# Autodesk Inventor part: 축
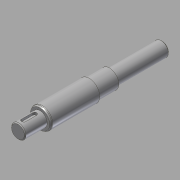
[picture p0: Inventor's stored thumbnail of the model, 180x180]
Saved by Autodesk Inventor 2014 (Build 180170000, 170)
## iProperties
Created: 2019-01
Part Number: 축
Material: 강철, 탄소
Document SubType Name: Modeling
Designer: mduedu
Density: 7.87 g/cm^3
Mass: 452.778 g
Surface Area: 120.904 cm^2
Volume: 57.5322 cm^3
Appearance: 강철
Author: mduedu
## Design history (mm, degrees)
sketch "스케치1"
  geometry: L1 (0, 0)-(26, 0); L2 (26, 0)-(26, 8.5); L3 (26, 8.5)-(0, 8.5); L4 (0, 8.5)-(0, 0); L5 (26, 0)-(84, 0); L6 (84, 0)-(84, 12.5); L7 (84, 12.5)-(26, 12.5); L8 (26, 12.5)-(26, 0); L9 (84, 0)-(108, 0); L10 (108, 0)-(108, 11); L11 (108, 11)-(84, 11); L12 (84, 11)-(84, 0); L13 (108, 0)-(170, 0); L14 (170, 0)-(170, 8.5); L15 (170, 8.5)-(108, 8.5); L16 (108, 8.5)-(108, 0)
  constraints: 32 end point, 8 parallel, 4 horizontal, 4 perpendicular
  dimensions: "d0" = 170 distance between parallel lines of L14 L4; "d2" = 26 distance of L2.end L3.end; "d3" = 24 distance of L10.end L11.end; "d4" = 62 distance of L14.end L15.end; "d5" = 17 diameter of L3 L1; "d6" = 25 diameter of L7 L5; "d7" = 22 diameter of L11 L9; "d8" = 17 diameter of L15 L13
revolve "회전1" sketch "스케치1" stored, may be unused: angle "d9" = 90 deg
node "작업 평면1"
sketch "스케치2" dims "d13" = 18
  geometry: L1 (6.5, -2.5)-(-6.5, -2.5); L2 (-6.5, -2.5)-(-6.5, 2.5); L3 (-6.5, 2.5)-(6.5, 2.5); L4 (6.5, 2.5)-(6.5, -2.5); L5 (13, 8.5)-(13, -8.5) reference; 3 further points
  constraints: 8 end point, 2 midpoint, 2 parallel, 2 vertical alignment, 1 horizontal, 1 horizontal alignment, 1 perpendicular, 4 other
  dimensions: "d10" = 5 distance between parallel lines of L3 L1; "d12" = 4 dimension on L5
extrude "돌출1" cut sketch "스케치2" distance "d14" = 3; taper "d15" = 0 deg
node "작업 평면2"
sketch "스케치3" dims "d19" = 18
  geometry: L1 (-24.5, -2.5)-(-11.5, -2.5); L2 (-11.5, -2.5)-(-11.5, 2.5); L3 (-11.5, 2.5)-(-24.5, 2.5); L4 (-24.5, 2.5)-(-24.5, -2.5); L5 (-31, 8.5)-(-31, -8.5) reference; 3 further points
  constraints: 8 end point, 2 midpoint, 2 parallel, 2 vertical alignment, 1 horizontal, 1 horizontal alignment, 1 perpendicular, 4 other
  dimensions: "d16" = 5 distance between parallel lines of L3 L1; "d18" = 4 dimension on L5
extrude "돌출2" cut sketch "스케치3" distance "d20" = 3; taper "d21" = 0 deg
chamfer "모따기1" distance "d22" = 1; stored, may be unused: second distance "d23" = 2, angle "d24" = 45 deg
chamfer "모따기2" distance "d25" = 2; stored, may be unused: second distance "d26" = 2, angle "d27" = 30 deg
fillet "모깎기2" dims "d30" = 2
node "솔리드1"
